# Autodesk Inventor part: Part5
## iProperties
Created: 2002-04
Part Number: Part5
Document SubType Name: Sheet Metal
Control State: 0
Master: False
Checked Out: False
Shininess: 77.0
Angle Display Precision: 2
Document Length Units: 11269
Document Angle Units: 11279
Document Time Units: 11290
Document Mass Units: 11283
Document Length Units Precision: 3
Document Angle Units Precision: 2
Density: 0.0
Volumn: 0.0
Area: 0.0
PropertySet Name: Model Information
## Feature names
1. Plate1
2. Plate7
3. Bend7
4. Plate8
5. Bend8
